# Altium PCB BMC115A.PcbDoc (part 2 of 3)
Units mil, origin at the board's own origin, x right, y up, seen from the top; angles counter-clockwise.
Board outline 5500 x 3200 mil, 4 copper layers (Top Layer, Signal Layer 1, Signal Layer 2, Bottom Layer), stack 61.6 mil thick; 199 components, 81 nets, 456 pads, 1349 vias.
Unrouted connection lines stored in the file: 741.
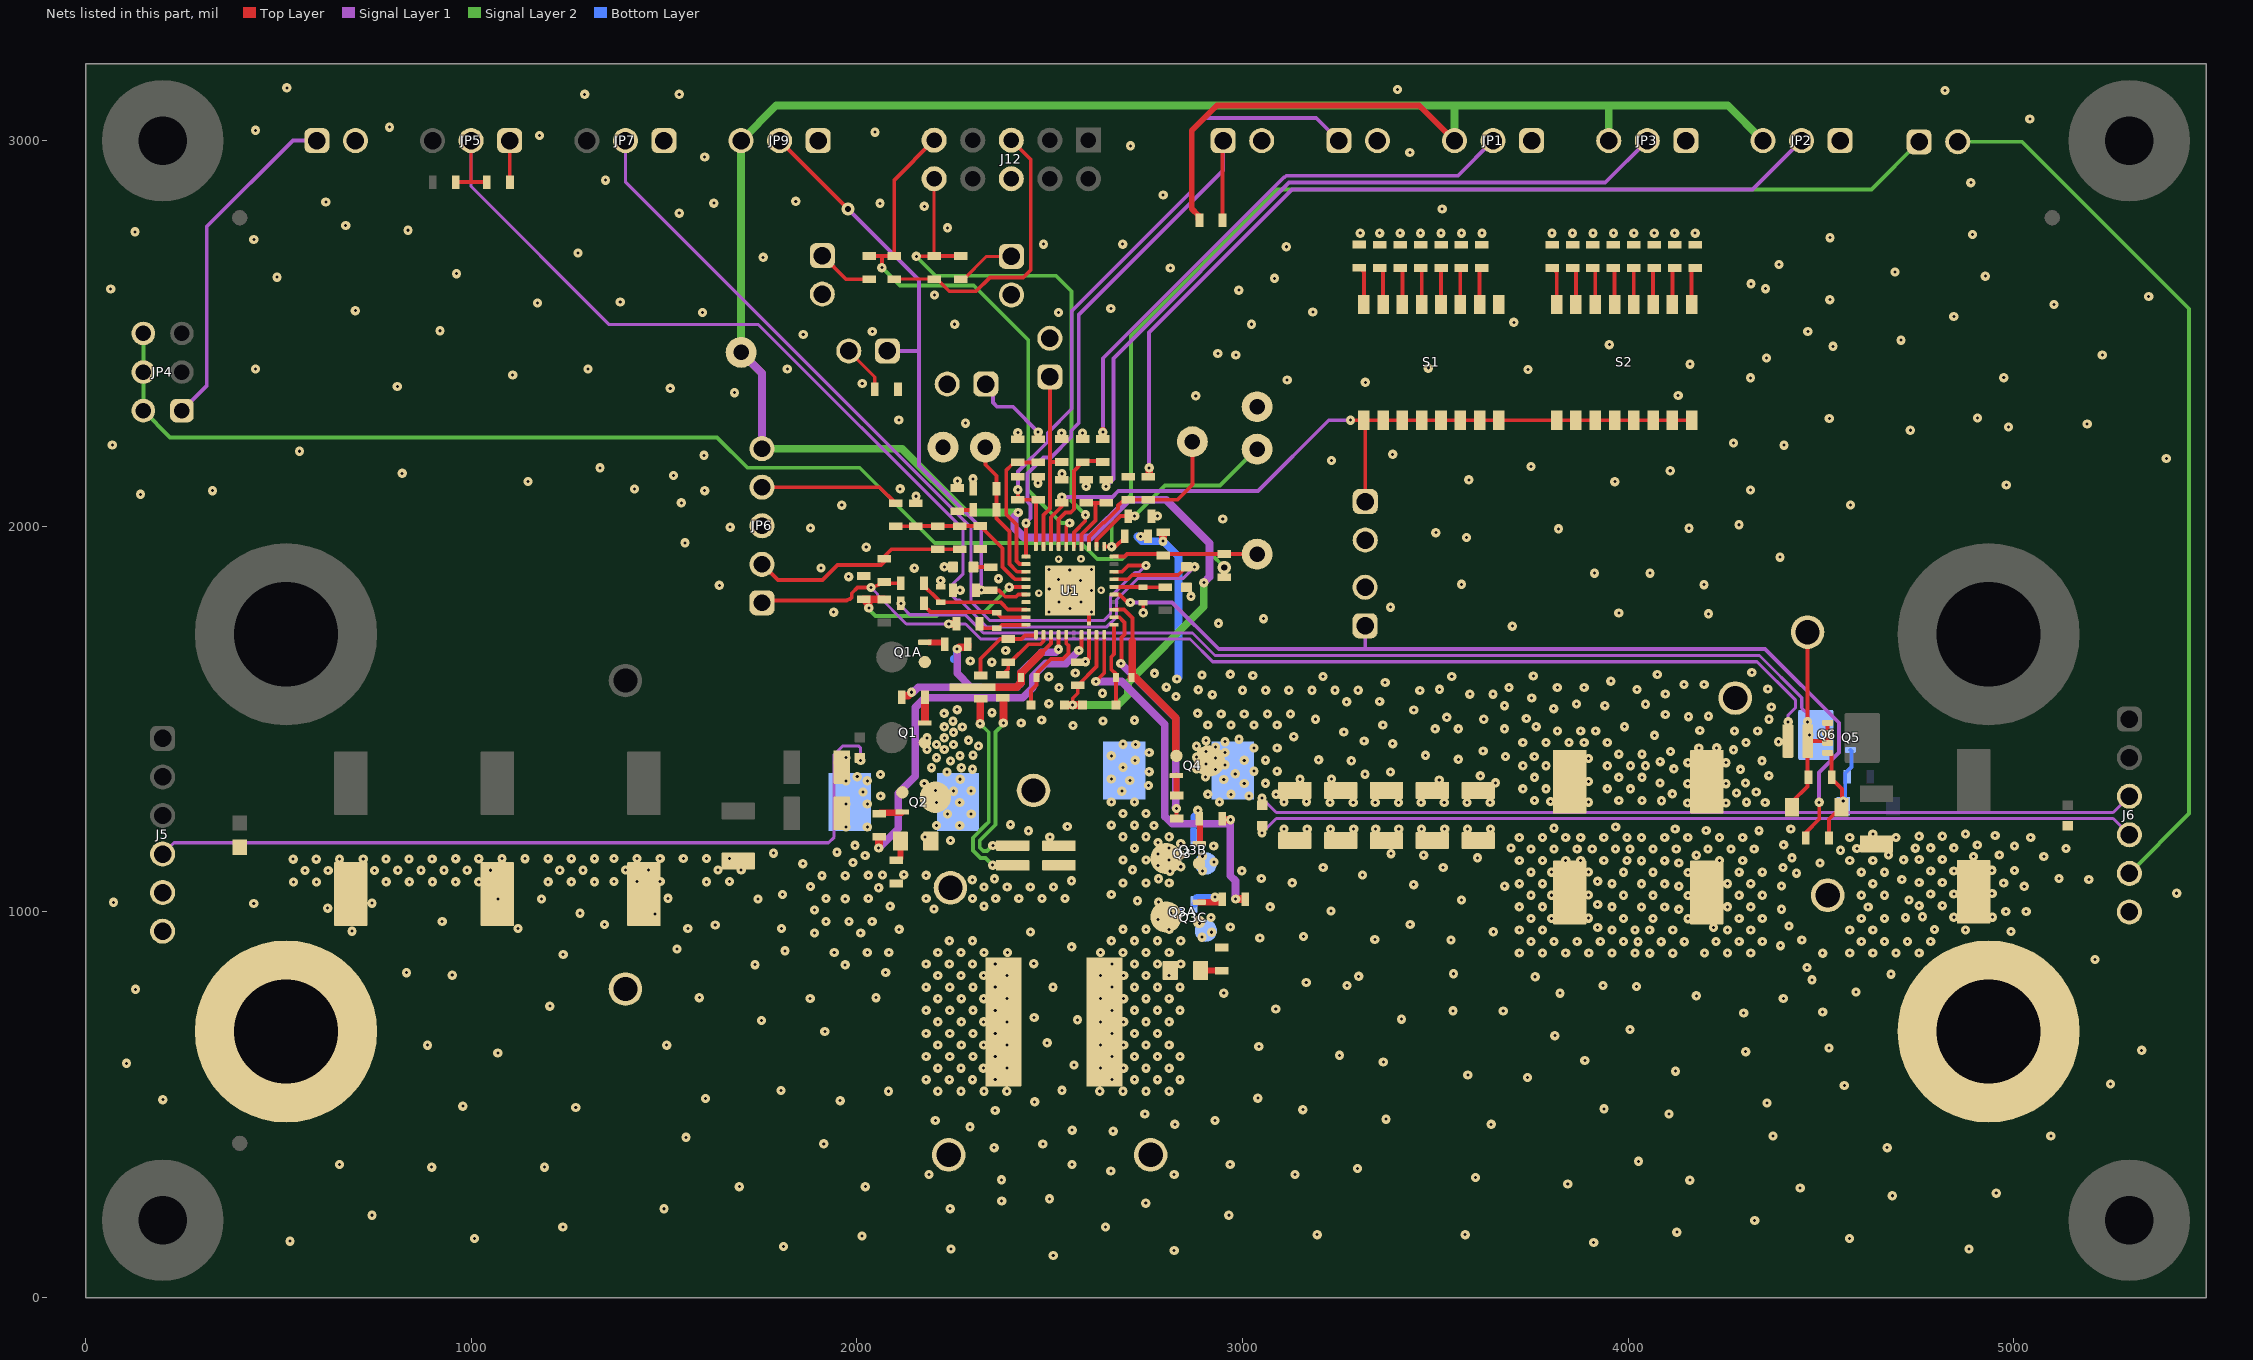
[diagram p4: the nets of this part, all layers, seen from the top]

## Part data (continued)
R30 R51: library part CMP-0023250-5, "RES, 6.49 k, 1%, 0.1 W, 0603", Manufacturer=Yageo, Power_W=100mW, Supplier Part Number 1=311-6.49KHRCT-ND, TempCo="100 ppm/C", Tolerance_%=1%, Value2=0.1W, Value_Code=6k49, ValueDisplayed=6.49k
R31 R52: library part CMP-0023307-5, "RES, 8.25 k, 1%, 0.1 W, 0603", Manufacturer=Yageo, Power_W=100mW, Supplier Part Number 1=311-8.25KHRCT-ND, TempCo="100 ppm/C", Tolerance_%=1%, Value2=0.1W, Value_Code=8k25, ValueDisplayed=8.25k
R32: library part CMP-0022000-4, "RES, 10.5 k, 1%, 0.1 W, AEC-Q200 Grade 0, 0603", Manufacturer=Vishay-Dale, Power_W=100mW, Supplier Part Number 1=541-10.5KHCT-ND, TempCo="100 ppm/C", Tolerance_%=1%, Value2=0.1W, Value_Code=10k5, ValueDisplayed=10.5k
R33: library part CMP-0022790-5, "RES, 13.3 k, 1%, 0.1 W, 0603", Manufacturer=Yageo, Power_W=100mW, Supplier Part Number 1=311-13.3KHRCT-ND, TempCo="100 ppm/C", Tolerance_%=1%, Value2=0.1W, Value_Code=13k3, ValueDisplayed=13.3k
R34: library part CMP-0022079-4, "RES, 16.2 k, 1%, 0.1 W, AEC-Q200 Grade 0, 0603", Manufacturer=Vishay-Dale, Power_W=100mW, Supplier Part Number 1=541-16.2KHCT-ND, TempCo="100 ppm/C", Tolerance_%=1%, Value2=0.1W, Value_Code=16k2, ValueDisplayed=16.2k
R35: library part CMP-0022905-5, "RES, 20.5 k, 1%, 0.1 W, 0603", Manufacturer=Yageo, Power_W=100mW, Supplier Part Number 1=311-20.5KHRCT-ND, TempCo="100 ppm/C", Tolerance_%=1%, Value2=0.1W, Value_Code=20k5, ValueDisplayed=20.5k
R36: library part CMP-0022237-4, "RES, 24.9 k, 1%, 0.1 W, AEC-Q200 Grade 0, 0603", Manufacturer=Vishay-Dale, Power_W=100mW, Supplier Part Number 1=541-24.9KHCT-ND, TempCo="100 ppm/C", Tolerance_%=1%, Value2=0.1W, Value_Code=24k9, ValueDisplayed=24.9k
R37: library part CMP-0022324-4, "RES, 30.1 k, 1%, 0.1 W, AEC-Q200 Grade 0, 0603", Manufacturer=Vishay-Dale, Power_W=100mW, Supplier Part Number 1=541-30.1KHCT-ND, TempCo="100 ppm/C", Tolerance_%=1%, Value2=0.1W, Value_Code=30k1, ValueDisplayed=30.1k
R38: library part CMP-0022352-4, "RES, 35.7 k, 1%, 0.1 W, AEC-Q200 Grade 0, 0603", Manufacturer=Vishay-Dale, Power_W=100mW, Supplier Part Number 1=541-35.7KHCT-ND, TempCo="100 ppm/C", Tolerance_%=1%, Value2=0.1W, Value_Code=35k7, ValueDisplayed=35.7k
R45: library part CMP-0022751-4, "RES, 10.0, 1%, 0.1 W, 0603", Manufacturer=Yageo, Power_W=100mW, Supplier Part Number 1=311-10.0HRCT-ND, TempCo="100 ppm/C", Tolerance_%=1%, Value2=0.1W, Value_Code=10R0, ValueDisplayed=10.0
R53: library part CMP-0025771-4, "RES, 2.7 k, 5%, 0.1 W, AEC-Q200 Grade 0, 0603", Manufacturer=Vishay-Dale, Power_W=100mW, Supplier Part Number 1=541-2.7KGCT-ND, TempCo="200 ppm/C", Tolerance_%=5%, Value2=0.1W, Value_Code=2k70, ValueDisplayed=2.7k
R54: library part CMP-0022410-4, "RES, 40.2 k, 1%, 0.1 W, AEC-Q200 Grade 0, 0603", Manufacturer=Vishay-Dale, Power_W=100mW, Supplier Part Number 1=541-40.2KHCT-ND, TempCo="100 ppm/C", Tolerance_%=1%, Value2=0.1W, Value_Code=40k2, ValueDisplayed=40.2k
R55: library part CMP-0025810-4, "RES, 43 k, 5%, 0.1 W, AEC-Q200 Grade 0, 0603", Manufacturer=Vishay-Dale, Power_W=100mW, Supplier Part Number 1=541-43KGCT-ND, TempCo="200 ppm/C", Tolerance_%=5%, Value2=0.1W, Value_Code=43k0, ValueDisplayed=43k
R60: library part CMP-0022852-5, "RES, 18.0 k, 1%, 0.1 W, 0603", Manufacturer=Yageo, Power_W=100mW, Supplier Part Number 1=311-18.0KHRCT-ND, TempCo="100 ppm/C", Tolerance_%=1%, Value2=0.1W, Value_Code=18k0, ValueDisplayed=18.0k
S1 S2: library part CMP-0002229-1, "Switch, SPST, 8 Pos, 25mA, 24VDC, SMD", CurrentRating_mA=25A, Manufacturer="CTS Electrocomponents", Supplier Part Number 1=CT2188LPST-ND
SH-JP1 SH-JP2 SH-JP3 SH-JP4 SH-JP5 SH-JP6 SH-JP7 SH-JP8 SH-JP9 SH-JP10 SH-JP11 SH-JP12: library part CMP-0078738-1, "Single Operation 2.54mm Pitch Open Top Jumper Socket", Manufacturer=Harwin, Supplier Part Number 1=952-2881-ND
TP1: library part CMP-0055147-2, "Test Point, Multipurpose, Red, TH", Color=Red, Manufacturer="Keystone Electronics", Supplier Part Number 1=36-5010-ND
TP2 TP8: library part CMP-0055150-2, "Test Point, Multipurpose, Orange, TH", Color=Orange, Manufacturer="Keystone Electronics", Supplier Part Number 1=36-5013-ND
TP3 TP4: library part CMP-0055148-2, "Test Point, Multipurpose, Black, TH", Color=Black, Manufacturer="Keystone Electronics", Supplier Part Number 1=36-5011-ND
TP5 TP6 TP9: library part CMP-0055149-2, "Test Point, Multipurpose, White, TH", Color=White, Manufacturer="Keystone Electronics", Supplier Part Number 1=36-5012-ND
TP7: library part CMP-0055159-2, "Test Point, Multipurpose, Grey, TH", Color=Grey, Manufacturer="Keystone Electronics", Supplier Part Number 1=36-5128-ND
TP10 TP11 TP12 TP13 TP15: library part CMP-0055141-2, "Test Point, Miniature, Yellow, TH", Color=Yellow, Manufacturer="Keystone Electronics", Supplier Part Number 1=36-5004-ND
TP14 TP16: library part CMP-0055138-2, "Test Point, Miniature, Black, TH", Color=Black, Manufacturer="Keystone Electronics", Supplier Part Number 1=36-5001-ND
U1: library part CMP-0120007-1, "48-V 4 Switch Buck-Boost Controller with I2C interface", Manufacturer="Texas Instruments", Max Supply Voltage=48V, Min Supply Voltage=3.3V, Nominal Supply Current=25uA, Operating Temperature Range="-40°C to +150°C", Output Voltage=3.3-48V, Switching Frequency=100-2200kHz
ZZ2: library part CMP-0077236-1
ZZ3: library part CMP-0077237-1
ZZ4: library part CMP-0077238-1

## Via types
v1: diameter 24, hole 7.87, Top Layer to Bottom Layer, tented both sides, 1320 vias
v2: diameter 19.68, hole 7.87, Top Layer to Bottom Layer, tented both sides, 17 vias
v3: diameter 24, hole 8, Top Layer to Bottom Layer, tented both sides, 8 vias
v4: diameter 34, hole 16, Top Layer to Bottom Layer, tented both sides, 2 vias
v5: diameter 19.68, hole 7.87, Top Layer to Bottom Layer, 2 vias

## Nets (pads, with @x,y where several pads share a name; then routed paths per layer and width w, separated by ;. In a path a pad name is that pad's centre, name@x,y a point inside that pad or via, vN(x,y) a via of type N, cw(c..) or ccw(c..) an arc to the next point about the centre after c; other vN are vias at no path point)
AGND: C17.1 C18.2 C19.2 C20.2 C26.1 C27.2 C28.2 C29.1 C33.2 C34.2 C35.2 C36.2 C37.2 C40.2 C42.2 J7.2 J8.2 J9.2 J10.2 J11.2 J12.6 J14.2 JP1.1 JP2.1 JP3.1 JP5.1 JP6.3 JP7.1 JP8.2 JP9.1 JP11.2 JP12.2 NT1.2 R2.1 R15.1 R18.1 R20.1 R21.1 R24.1 R25.1 R26.1 R27.1 R28.1 R29.1 R30.1 R31.1 R32.1 R33.1 R34.1 R35.1 R36.1 R37.1 R38.1 R53.1 R54.1 R60.1 S1.1 TP14.1 TP16.1 U1.17 U1.41 | length 750.5
  Top Layer w10: JP5.1@1100,3005.59 JP5.1@1100,3000 1100,2893.28 R15.1@1100.61,2892.68 ; R21.1@2417.7,2226.09 v1(2417.7,2242.78) ; v1(2469.92,2111.69) 2469.92,2128.38 R54.1@2470.26,2128.72 ; R53.1@2531.4,2120.8 2531.4,2135.12 v1(2532.47,2136.2) ; v2(2553,1786.46) v2(2553,1833) ; NT1.2@2602.22,1748.34 U1.41@2602.22,1777.88 ; U1.41@2602.54,1827.42 v2(2608.12,1833) ; C26.1@2742.37,1801.95 2742.89,1801.43 v1(2742.89,1775.77)
  Top Layer w20: v1(2736.27,1973.26) v1@2744.74,1973.26 ; v1(2794.32,1961.47) C29.1@2794.32,1980.94
  Bottom Layer w10: v1@2785.32,1961.47 v1@2789.82,1956.97 ; v1@2794.32,1956.97 v1(2794.32,1961.47)
  Bottom Layer w20: v1@2727.8,1973.26 2739.58,1961.47 v1@2785.32,1961.47 ; v1(2794.32,1961.47) 2834.46,1921.33 2834.46,1751.45 2834.46,1608.32 v1(2830.06,1603.93)
  other v1: 3699.82,1740.92 2938,1748.25 3054.7,1760.48 4208.74,1772.93 3976.22,1775.35 1940,1777.37 3384.3,1790.15 2866.87,1818.39 2268.12,1834.12 1643.69,1846.89 3567.96,1849.43 4196.73,1848.52 2217.64,1859.28 2367.43,1864.12 1978.89,1869.36 3913,1878.43 4057.2,1878.43 2149.19,1891.48 1907.45,1891.69 2227.11,1894.88 4394,1920 2024.57,1945.95 1554.27,1957.1 3581,1971 3501.46,1983.47 3819.87,1993.39 1880,1995.26 4158.2,1994.85 1671.75,1997.74 4287.79,2004 2949,2018.96 2780.08,2026.62 1961.04,2054.59 4577,2055 1544.89,2060.75 2153.61,2077.87 142.76,2082.92 329.47,2092.38 1605.68,2092.38 4317.87,2094.39 1423.63,2096.98 2112.63,2097.1 2594.9,2103.69 4981,2107 1147.19,2116.01 3965.7,2115.61 2261.32,2117.3 3587.09,2120.47 2301.57,2123.05 1524.46,2131.42 821.05,2137.28 4109.45,2144.01 1333.99,2151.71 3748.31,2154.78 3231.3,2170.36 5396,2176 1603.56,2184.13 3389.62,2186.52 554.7,2194.57 4404.53,2210.22 69.5,2210.55 4273.26,2215.74 2531.21,2241.64 2585.06,2241.64 4731.91,2249 4986.36,2257.23 5190.55,2265.13 2282.15,2267.3 2108.95,2275.74 4521.89,2279.2 4906.36,2280.53 2879.03,2338.4 4130,2339 1683.03,2346.39 1516.34,2357.88 808.47,2362.16 2014.15,2370.46 3318.61,2373.33 3116.18,2379.61 4317.87,2384.87 4974.29,2385.25 1107.63,2392.53 3740.61,2406.25 441,2407.8 1303.19,2407.81 1820,2407.81 3482.22,2410.07 4160.45,2420.36 4359.05,2436.35 2983.05,2443.91 5230,2444 2936.19,2447.84 4531.3,2466.78 3951.54,2470.99 4707.7,2482.66 1861.22,2497.46 2040.36,2504.95 4466.2,2505.04 918.97,2507.03 2253.75,2523.87 3023.48,2523.87 3703.74,2528.79 4844.8,2543.85 1600,2554.43 2523.35,2554.43 3182.74,2555.6 699.61,2558.99 2658.69,2564.84 5104.35,2575.07 1172.1,2579.13 1386.67,2581.55 4523.2,2587.48 5350,2596 2201.71,2599.94 2990.7,2612.39 65.22,2615.39 4356.47,2616.11 4318.82,2628.86 3083.19,2643 496.54,2645.86 4926.56,2648.5 962,2655 4692.23,2659.58 2813,2670 4391.69,2678.8 1757.39,2697.35 1277.24,2708.96 3113.92,2724.83 2484.4,2731.6 2689.41,2731.6 436.5,2743.89 4523.75,2748.47 4893.06,2756.42 3305.61,2760 3356,2760 3409,2760 3462,2760 3515,2760 3568,2760 3621,2760 3803,2760 3856,2760 3909,2760 3962,2760 4015,2760 4068,2760 4121,2760 4174,2760 128.58,2763.57 836.53,2767.7 2235,2774 674.65,2780.22 1539.59,2812 3518.03,2822.95 2175.13,2829.79 1629.17,2837.92 2060.46,2837.53 623.09,2841.07 1841.75,2842.72 2794.66,2858.75 4888.99,2891.02 1348.32,2897.44 1605.68,2957.29 3434,2969 2710.03,2986.57 1177.24,3013.64 2047.48,3021.84 441,3026.64 788,3034.95 5042.03,3056.39 1294.41,3120 1539.59,3120 4822.07,3129.89 3402.03,3132.39 522,3137
  other v2: 2497.88,1777.88 2608.12,1777.88 2524.33,1804.08 2581.35,1804.08 2472.01,1826.4 2633.77,1834.12 2499.08,1837.16 2580.27,1859.28 2523.47,1861.62 2552.26,1886.07 2497.88,1888.12 2608.12,1888.12 2523.35,1914.8 2581.35,1915.33
BIAS: C29.2 R57.1 TP15.1 U1.40 | length 382.5
  Top Layer w10: U1.40@2667.17,1921.58 2694.94,1921.58 2701.15,1927.79 ; 2694.71,1921.36 2701.15,1927.75 2794.32,1927.75 2954.56,1927.75 3037.84,1927.75 TP15.1@3038,1927.91
CDC: C42.1 J14.1 R54.2 U1.10 | length 1739.8
  Top Layer w10: v3(2417.7,2094.66) 2417.93,2094.43 C42.1@2417.93,2068.72 R54.2@2470.26,2068.72 2464.42,2062.87 U1.10@2464.42,1947.17
  Signal Layer 1 w10: v3(2417.7,2094.66) 2417.93,2094.89 2417.93,2142.03 2495.23,2219.33 2495.23,2242.29 2557.56,2304.62 2557.56,2558.56 2868.51,2869.51 2868.51,3026.04 2901.13,3058.67 3191.33,3058.67 J14.1@3250,3000
CFG2: J8.1 R53.2 S1.9 S1.10 S1.11 S1.12 S1.13 S1.14 S1.15 S1.16 S2.9 S2.10 S2.11 S2.12 S2.13 S2.14 S2.15 S2.16 U1.8 | length 2064.1
  Top Layer w10: U1.8@2503.79,1947.17 2503.79,2023.26 2531.4,2050.87 R53.2@2531.4,2060.8 2531.4,2075.56 v1(2531.84,2076.01) ; v1(3280,2275) S1.9@3315,2275 ; J8.1@3318.61,2068.72 3318.61,2271.39 S1.9@3315,2275 ; S2.16@4165,2275 S2.15@4115,2275 S2.14@4065,2275 S2.13@4015,2275 S2.12@3965,2275 S2.11@3915,2275 S2.10@3865,2275 S2.9@3815,2275 S1.16@3665,2275 S1.15@3615,2275 S1.14@3565,2275 S1.13@3515,2275 S1.12@3465,2275 S1.11@3415,2275 S1.10@3365,2275 3318.61,2275 S1.9@3315,2275
  Signal Layer 1 w10: v1(2531.84,2076.01) 2662.84,2076.01 2678.13,2091.3 2693.8,2091.3 2694.08,2091.59 2811.39,2091.59 2811.67,2091.3 3040.23,2091.3 3223.93,2275 v1(3280,2275)
COMP: C19.1 R19.2 TP13.1 U1.13 | length 380.1
  Top Layer w10: TP13.1@2333.66,2205.39 2333.66,2159.41 2362.19,2130.89 C19.1@2362.19,2097.1 R19.2@2362.19,2042.59 2362.19,2020.25 2396,1986.44 2396,1902.16 2415.94,1882.21 U1.13@2438.83,1882.21
CSA/SW1: C21.2 R11.1 U1.22 | length 169.5
  Top Layer w10: R11.1@2378,1615 2392.68,1629.68 C21.2@2392.68,1647.64 2398.68,1647.64 2445.19,1694.14 2476.26,1694.14 2484.1,1701.99 U1.22@2484.1,1718.83
CSB: C21.1 R12.1 U1.21 | length 212.8
  Top Layer w10: R12.1@2321,1613 2321,1656.45 2372.19,1707.64 C21.1@2392.68,1707.64 2392.81,1707.52 2426.67,1707.52 2436.11,1716.96 2462.55,1716.96 U1.21@2464.42,1718.83
DRV1: J11.1 R55.1 U1.35 | length 2413.3
  Top Layer w10: U1.35@2667.17,1823.16 2681.33,1823.16 v1@2701.87,1802.62 ; R55.1@4461.1,1198.3 4461.1,1205.8 4495.79,1240.49 4495.79,1257.73 v1(4495.79,1284.1)
  Signal Layer 1 w10: v1@2701.87,1802.62 2817.82,1802.62 2938.57,1681.87 3318.61,1681.87 ; J11.1@3318,1741.92 3318.61,1741.31 3318.61,1681.87 ; v1@4495.16,1276.51 4495.16,1361.86 4546.75,1413.45 4546.75,1490.64 4355.52,1681.87 3318.61,1681.87
  other v1: 2709.27,1802.62
DTRK: C36.1 R50.2 U1.4 | length 181.3
  Top Layer w10: U1.4@2582.53,1947.17 2582.53,1978.27 2619.5,2015.24 2619.5,2060.8 ; C36.1@2594.9,2060.8 2614.58,2060.8 2619.5,2060.8 ; R50.2@2647.23,2060.8 2619.5,2060.8
EN/UVLO: C28.1 JP5.2 R14.1 R15.2 U1.37 | length 3114
  Top Layer w8: 1000,2892.68 JP5.2@1000,3000
  Top Layer w10: R14.1@960.36,2892.68 1000,2892.68 R15.2@1040.61,2892.68 ; U1.37@2667.17,1862.53 2703.21,1862.53 2714.33,1873.65 2833.72,1873.65 C28.1@2854.99,1894.92 ; v1(2876.2,1894.88) v1(2876.2,1894.88)
  Top Layer w20: C28.1@2854.99,1894.92 v1(2876.2,1894.88)
  Signal Layer 1 w8: JP5.2@1000,3000 1000,2881.06 1358.18,2522.88 1745.1,2522.88 2275.8,1992.18 2275.8,1876.98 2243.24,1844.42 2243.24,1823.81 2257.82,1809.24 2266.29,1809.24 2336.27,1739.27 2648.52,1739.27 2673.36,1764.1 2673.36,1809.7 2727.78,1864.12 2845.44,1864.12 v1(2876.2,1894.88)
FB: C16.2 C37.1 R1.1 R2.2 R46.1 U1.14 | length 424.8
  Top Layer w10: R46.1@2100.43,1999.98 C37.1@2153.05,1999.98 2153.48,2000.42 C16.2@2209.91,2000.42 R1.1@2266.51,2000.42 2266.96,2000.86 R2.2@2320.21,2000.86 2378.12,1942.95 2378.12,1893.95 2405,1867.07 2405.68,1867.07 2410.22,1862.53 U1.14@2438.83,1862.53
FLT: J9.1 R16.1 U1.11 | length 1515.7
  Top Layer w10: U1.11@2438.83,1921.58 v1(2438.83,2007.96) ; R16.1@2948.51,2793.22 2948.51,2998.51 J9.1@2950,3000
  Signal Layer 1 w10: v1(2438.83,2007.96) 2438.83,2008.78 2450.87,2020.82 2450.87,2055.47 2442.57,2063.76 2442.57,2137.09 2484.2,2178.71 2503.46,2178.71 2556.08,2231.33 2556.08,2247.84 2575.44,2267.19 2575.44,2548.27 2950,2922.83 J9.1@2950,3000
GND: C1.2 C2.1 C3.1 C4.1 C5.1 C6.1 C7.2 C8.1 C9.1 C10.1 C11.1 C12.1 C13.1 C14.1 C15.1 C31.2 C32.2 C38.1 C39.1 C41.1 D2.2 J3.1 J4.1 J5.4 J5.5 J5.6 J6.4 J6.5 J6.6 J13.2 NT1.1 Q2.1-2-3 Q3.1-2-3 Q3A.1-2-3 Q3B.1-2-3-4 Q3C.1-2-3-4 R13.1 R39.1 TP3.1 TP4.1 U1.28 | length 6771
  Top Layer w10: v1(2498,1540) v1@2498.78,1540.78 ; v1(2593.31,1648.89) 2601.95,1657.53 2601.95,1673.61 2602.21,1673.88 U1.28@2602.21,1718.83
  Top Layer w25: C2.1@1952.58,1387.56 C2.1@1967.22,1372.92
  Signal Layer 1 w8: J5.4@200,1150 229.3,1179.3 1926.6,1179.3 1941.24,1193.94 1941.24,1204.22 1941.36,1204.35 1941.36,1408.37 1962.93,1429.94 2005.4,1429.94 2010.08,1425.26 v1(2010.08,1392.48) ; v1(3051,1205) 3088.04,1242.04 5257.96,1242.04 J6.4@5300,1200
  Signal Layer 2 w10: J13.2@4855,2997 5022,2997 5455,2564 5455,1255 J6.5@5300,1100
  other v1: 2509.48,109.05 2823.15,121.96 2244.33,125.84 4884.1,125.84 1809.98,132.58 3911.03,142.68 530.5,146.05 1008.62,152.78 4574.34,152.78 2013.8,159.39 3193.84,162.88 3577.69,162.88 4126.52,169.61 1237.58,183.08 2645.01,183.08 4328.54,199.92 742.62,213.39 2964.88,213.39 1500.21,230.22 2242.28,230.39 2749.39,244.8 2375.65,250.42 2500,256 4685.45,263.89 4954.81,270.63 4446.39,284.09 1695.5,287.46 2022.11,287.46 3843.68,294.2 4160.19,304.3 3604.62,311.03 3136.6,318.88 3298.22,334.6 897.51,337.97 1190.44,337.97 658.45,344.7 2558.1,344.7 2968.25,344.7 4026.89,353.33 4671.98,388.47 2482.53,398.02 1914.36,398.57 1557.45,415.41 4375.68,418.78 5096.23,418.78 2558.42,434.1 3645.03,449.08 2929,458.86 3372.3,462.55 4106.31,476.02 3156.8,487.23 3937.96,489.49 1271.25,492.85 978.32,496.22 4360.15,504.61 2461.38,507.5 1957.01,510.5 200.53,513.05 1607.96,516.42 3040.01,516.95 2082.22,534.89 1803.25,536.62 2532.3,537.36 4560.87,550.09 5251.11,553.46 3739.31,570.29 3584.42,577.03 4123.34,587 2563.4,603.3 106.25,607.33 3365.56,610.7 3888.02,614.59 3251.71,627.96 1069.23,634.27 4304.97,637.64 5331.92,641 4521.1,646.78 3042.59,651.2 887.05,654.47 1506.95,654.47 2493.73,660.53 3810.23,678.97 1916.99,689.92 4005.3,694.88 1752.74,718.45 2572.11,720.25 3412.7,721.81 2460.14,726.47 4299.79,737.99 4504.83,740.17 3545.99,743.35 3676.39,742.84 3086.48,748.01 1203.91,755.48 1879.04,775.27 4402.62,775.68 1591.7,777.7 2049.95,777.7 4177.02,782.42 2951.65,789.15 3823.48,789.15 4591.17,792.52 129.82,799.25 2508.66,804.85 4022.15,806.4 3271.28,809.36 3934.97,809.08 3165.56,817.2 4476.84,823.83 3759.26,831.88 3301.59,832.92 951,836 4682.06,838.59 3547.38,839.66 832.64,842.53 2075,843 4464.32,856.02 1735.91,863.23 1969.91,862.89 2458.89,865.82 5210.71,876.7 1238.65,889.47 3718.2,893.16 3778.2,893.16 3838.2,893.16 3898.2,893.16 3958.2,893.16 4018.2,893.16 4055.99,892.91 4115.99,892.91 4198.2,893.16 4258.2,893.16 4318.2,893.16 4504.83,892.91 4574.92,893.16 4634.92,893.16 4694.92,893.16 4754.92,893.16 1941.57,895 2027.35,894.89 2083.08,895 1813.72,899.04 1533.88,903.63 2557.18,909.36 4395.12,912.43 3748.2,923.16 3808.2,923.16 3868.2,923.16 3928.2,923.16 3988.2,923.16 4025.99,922.91 4085.99,922.91 4145.99,922.91 4228.2,923.16 4288.2,923.16 4348.2,923.16 4604.92,923.16 4664.92,923.16 4724.92,923.16 4784.92,923.16 3540.63,927.11 4450.81,927.11 3343.46,928.45 3045.17,932.6 2894.99,934.49 3158.36,936.5 1890.08,945 2010,945 2920.25,947.28 2450.18,947.93 3650.61,948.57 4993.25,949.05 690.73,950 3718.2,953.16 3778.2,953.16 3958.2,953.16 4018.2,953.16 4055.99,952.91 4115.99,952.91 4258.2,953.16 4318.2,953.16 4574.92,953.16 4634.92,953.16 4874.92,953.16 4794.92,954.16 2109.98,954.89 1121.7,957 1562,957 1805.06,956.86 3921.39,959.25 4221.39,959.25 2968.79,960.86 4417.38,963.33 1633.01,966.16 1345.66,967.61 3434.93,967.61 2888.17,970.51 924.88,975.12 1920.08,975 1980,975 2040,975 4155.62,982.32 3748.2,983.16 3801.72,983.16 3988.2,983.16 4064.99,982.91 4288.2,983.16 4348.2,983.16 4604.92,983.16 4664.92,983.16 3897.57,983.75 4719.21,985.11 2918.68,985.67 4844.92,986.16 4945.35,986.19 4763.5,987.44 1476.64,994.54 1282.29,996.53 4979.56,1000.86 5032.48,1000.84 3229.76,1002.3 1890.08,1005 4131.8,1006.82 4397.76,1006.88 628,1009.66 3071.93,1013.31 3718.2,1013.16 3778.2,1013.16 3958.2,1013.16 4034.99,1012.91 4094.99,1012.91 4258.2,1013.16 4318.2,1013.16 4622.6,1012.95 2086.49,1014.9 4754.92,1016.16 4814.92,1016.16 3921.39,1019.25 436.22,1021.48 742.62,1022.68 72.58,1024.85 3567.96,1030.7 4728.28,1030.7 1069.23,1033.28 1182.48,1033.28 1744.02,1033.28 1970.08,1034 1510.41,1035.23 1920.08,1035 2030,1034.89 4155.62,1042.32 3748.2,1043.16 3801.72,1043.16 3988.2,1043.16 4064.99,1042.91 4288.2,1043.16 4348.2,1043.16 4604.92,1043.16 4664.92,1043.16 3897.57,1043.75 1807.31,1044.89 4784.92,1046.16 4844.92,1046.16 4944.37,1047.77 5422.83,1048.42 2056.71,1062.59 1880,1066 5027.46,1066.35 3680.12,1066.6 4131.8,1066.82 4397.76,1066.88 3444.06,1070.63 3718.2,1073.16 3778.2,1073.16 3958.2,1073.16 4034.99,1072.91 4094.99,1072.91 4258.2,1073.16 4318.2,1073.16 4634.92,1073.16 3129.23,1075.35 4974.12,1075.21 4754.92,1076.16 4814.92,1076.16 539.1,1077.58 599.1,1077.58 779.73,1077.99 839.73,1077.99 899.73,1077.99 959.73,1077.99 1019.73,1077.99 1199.73,1077.99 1259.73,1077.99 1319.73,1077.99 1610.22,1077.99 1370.22,1078.76 1430.22,1078.76 1490.22,1078.76 1670.22,1078.76 3921.39,1079.25 4710.12,1084.22 5194.99,1084.16 3049.04,1086.89 5117.38,1086.87 1910.08,1094 1970.08,1094 2030,1094.89 2066.73,1095.85 3311.63,1095.56 2121.96,1096.53 4437.18,1100.49 4155.62,1102.32 3748.2,1103.16 3801.72,1103.16 3988.2,1103.16 4064.99,1102.91 4288.2,1103.16 4348.2,1103.16 4604.92,1103.16 4664.92,1103.16 3897.57,1103.75 2998.35,1106.44 4784.92,1106.16 4844.92,1106.16 569.1,1107.58 629.1,1107.58 749.1,1107.58 809.73,1107.99 869.73,1107.99 929.73,1107.99 989.73,1107.99 1049.73,1107.99 1229.73,1107.99 1289.73,1107.99 4944.12,1107.71 5002.36,1107.66 1400.22,1108.76 1460.22,1108.76 1640.22,1108.76 1700.22,1108.76 3209.33,1114.89 3520.51,1114.89 4401.79,1115.39 1860.08,1125 4131.8,1126.82 4497.95,1126.82 1989.94,1128.39 3718.2,1133.16 3778.2,1133.16 3838.2,1133.16 3877.2,1133.16 3937.2,1133.16 3997.2,1133.16 4034.99,1132.91 4094.99,1132.91 4237.2,1133.16 4297.2,1133.16 4574.92,1133.16 4634.92,1133.16 4714.92,1135.16 4754.92,1136.16 4814.92,1136.16 538.35,1136.82 598.35,1136.82 658.35,1136.82 720.22,1137.23 778.98,1137.23 838.98,1137.23 898.98,1137.23 959.73,1137.99 1019.73,1137.99 1079.73,1137.99 1139.73,1137.99 1199.73,1137.99 1259.73,1137.99 1319.73,1137.99 1370.22,1138.76 1430.22,1138.76 1490.22,1138.76 1550.22,1138.76 1610.22,1138.76 1670.22,1138.76 3609.42,1140.37 4425.01,1140.16 4895.97,1143.62 5078.28,1143.57 2021.8,1146.44 3469.93,1147.08 4177.02,1147.08 4675.58,1147.47 4962.94,1147.47 3385.43,1151.1 1784,1152.37 1948.65,1154.92 4550.67,1159.84 3748.2,1163.16 3808.2,1163.16 3868.2,1163.16 3907.2,1163.16 3967.2,1163.16 4004.99,1162.91 4064.99,1162.91 4124.99,1162.91 4207.2,1163.16 4267.2,1163.16 4327.2,1163.16 4593.37,1164.27 5135.6,1164.27 4744.92,1165.16 3696.22,1165.86 4784.92,1166.16 4844.92,1166.16 5002.04,1170.93 1995.43,1172.72 4905.89,1173.33 4403.52,1173.97 3718.2,1193.16 3778.2,1193.16 3838.2,1193.16 3877.2,1193.16 3937.2,1193.16 3997.2,1193.16 4034.99,1192.91 4094.99,1192.91 4154.99,1192.91 4237.2,1193.16 4297.2,1193.16 4574.92,1193.16 4694.92,1193.16 5044.12,1193.21 4754.92,1196.16 4814.92,1196.16 4952.19,1198.3 4634.92,1201.76 4874.85,1202.05 4202.62,1211.03 4339.53,1210.57 3107.89,1214.92 3167.89,1214.92 3228.46,1214.92 3288.46,1214.92 3345.46,1214.92 3405.46,1214.92 3464.46,1214.92 3524.46,1214.92 3583.46,1214.92 3643.46,1214.92 4122.11,1215.12 4422.18,1214.92 3808.2,1216.94 1971.92,1220 2027.35,1220 3967.92,1220.12 1971.92,1280 2027.35,1280 2061.85,1300.32 2016.38,1310.81 1971.92,1340 2027.35,1340 2001.24,1350.55 2061.5,1356.35 1971.92,1400 2560.75,1483.26 2426.3,1490 2638.59,1495 2720.08,1496.81 2479.47,1497.7 2350.33,1516.5 2827.78,1558.31 2637.23,1566.99 2524.33,1581.97 2802.73,1582.63 2498,1609.89 2566.73,1619.34 2772.32,1618.65 2350.12,1647.49 2294.35,1650.53 2386.09,1677.64
  other v3: 2896.55,1106.59 2926.39,1129.34 2896.55,1144.38 2925.43,1170.68
HB1: C24.2 D3.1 U1.25 | length 239.8
  Top Layer w10: D3.1@2451.69,1540 2451.69,1574.03 2465.94,1588.28 2465.94,1608 2468.48,1610.54 2468.48,1620.37 2503.75,1655.64 2534.94,1655.64 2548.98,1669.68 2548.98,1690.39 2543.16,1696.21 U1.25@2543.16,1718.83
HB2: C25.2 D4.1 U1.31 | length 215.7
  Top Layer w10: U1.31@2667.17,1744.42 2667.17,1668.47 2659.92,1661.22 2659.92,1654.64 2659.92,1629.03 2672.04,1616.91 C25.2@2672.04,1608 ; D4.1@2672.31,1536.5 C25.2@2672.31,1607.74
HO1: R7.1 R58.1 U1.24 | length 699.8
  Top Layer w10: v1(2523.35,1680.84) 2523.47,1680.97 U1.24@2523.47,1718.83
  Top Layer w20: R7.1@2116.89,1556 2116.89,1560.33 2132.74,1560.33 v1(2142.01,1569.6) ; v1(2260.37,1682.02) 2261.46,1682.02 2266.08,1686.64 2288.08,1686.64 R58.1@2288.08,1694.14
  Signal Layer 1 w20: v1(2142.01,1569.6) 2145.8,1569.6 2159.14,1582.94 2296.05,1582.94 ; v1(2260.37,1682.02) 2260.37,1618.62 2296.05,1582.94 ; v1(2523.35,1680.84) 2515.77,1673.27 2479.21,1673.27 2425.94,1620 2425.94,1593.59 2415.29,1582.94 2296.05,1582.94
  Bottom Layer w20: 2251.12,1655.68 2258.62,1655.68 2258.62,1663.18 2259.61,1664.17 2259.61,1681.25 v1(2260.37,1682.02)
HO1_G: Q1.4 R7.2 | length 61.4
  Top Layer w20: Q1.4@2176.89,1494.63 R7.2@2176.89,1556
HO2: R8.1 U1.32 | length 604
  Top Layer w10: U1.32@2667.17,1764.1 2681.27,1764.1 2691.86,1753.52 2691.86,1753.33 2694.12,1751.07 2694.12,1719.22 2686.13,1711.22 2686.13,1650.67 v1@2679.79,1644.33 ; R8.1@2829.13,1242 v1@2829.13,1267.82
  Signal Layer 1 w20: v1(2684.79,1644.33) 2827.13,1502 2827.13,1270.8 v1@2826.75,1270.43
  other v1: 2828.97,1267.97
HO2_G: Q4.4 R8.2 | length 53.9
  Top Layer w10: R8.2@2826.85,1300.32 R8.2@2828.83,1302.3
  Top Layer w15: R8.2@2828.83,1302.3 Q4.4@2828.83,1353.45
ILIMCOMP: C33.1 JP9.2 JP10.1 R17.2 U1.16 | length 1602.9
  Top Layer w10: JP9.2@1800,3000 v4(1977.44,2822.56) ; C33.1@2309.35,1834.12 R17.2@2347.75,1834.12 2368.48,1834.12 2370.51,1832.09 2370.51,1831.89 2385.08,1817.32 2412.73,1817.32 2418.56,1823.16 U1.16@2438.83,1823.16
  Signal Layer 1 w10: v4(1977.44,2822.56) 2161.08,2638.92 2161.08,2454.69 ; JP10.1@2079.27,2454.69 2161.08,2454.69 ; v1(2322.86,1834.45) 2322.86,1995.15 2314.6,2003.4 2314.6,2003.94 2161.08,2157.46 2161.08,2454.69
ISNSN: C30.1 R43.1 U1.19 | length 282.9
  Top Layer w10: R43.1@2174.38,1800 2174.38,1793.86 2190.87,1777.37 2361.06,1777.37 C30.1@2362.79,1775.65 2374.33,1764.1 U1.19@2438.83,1764.1
ISNSP: C30.2 R42.1 U1.20 | length 128.8
  Top Layer w10: R42.1@2318.38,1747 2329.73,1735.65 C30.2@2362.79,1735.65 2368.01,1735.65 2376.78,1744.42 U1.20@2438.83,1744.42
LO1: R9.2 U1.27 | length 974.7
  Top Layer w10: v1(2575.89,1677.64) 2582.53,1684.28 U1.27@2582.53,1718.83
  Top Layer w20: v1(2056.81,1165.86) 2057.57,1166.62 2057.57,1187.81 R9.2@2058.6,1188.84
  Signal Layer 1 w20: v1(2056.81,1165.86) 2057.89,1165.86 2107.65,1215.62 2107.65,1307.93 2151.7,1351.98 2151.7,1529.97 2176.8,1555.06 2430.45,1555.06 2456.55,1581.17 2456.55,1611.19 2489.69,1644.33 2542.58,1644.33 v1(2575.89,1677.64)
LO1_G: Q2.4 R9.1 | length 61.2
  Top Layer w10: R9.1@2058.6,1254.84 R9.1@2060.99,1257.23 ; Q2.4@2116.45,1257.23 Q2.4@2118.14,1258.92
  Top Layer w16: R9.1@2060.99,1257.23 Q2.4@2116.45,1257.23
LO2: R10.2 R59.2 U1.30 | length 1018.5
  Top Layer w10: v1(2619.82,1597.43) 2641.58,1619.19 U1.30@2641.58,1718.83
  Top Layer w20: R10.2@2949,1238.94 v1(2969,1238.94) ; v1(2982.45,1033.22) R59.2@3007.58,1033.22
  Signal Layer 1 w20: v1(2619.82,1597.43) 2687.27,1597.43 2798.69,1486.01 2798.69,1247.58 2817.82,1228.45 2958.51,1228.45 ; v1(2969,1238.94) 2968.48,1238.42 2968.48,1094.07 2982.33,1080.22 2982.33,1033.34 v1(2982.45,1033.22)
LO2_G: Q3.4 Q3B.9 R10.1 | length 156.9
  Top Layer w10: Q3.4@2887.69,1176.67 Q3.4@2888,1176.97
  Top Layer w16: v1(2884.34,1263.33) 2884.34,1261.16 2886,1259.5 2886,1243.94 R10.1@2888,1241.94 ; Q3.4@2889.66,1181.39 R10.1@2889.66,1241.94
  Bottom Layer w16: Q3B.9@2873.11,1189.54 2873.11,1246.64 v1@2884.34,1257.86
MODE: C34.1 R47.2 U1.7 | length 305.2
  Top Layer w10: U1.7@2523.47,1947.17 2523.47,2017.67 2535.88,2030.07 2541.68,2035.87 2554.72,2035.87 2562.84,2044 2562.84,2143.53 C34.1@2585.69,2166.38 ; C34.1@2585.69,2169.38 2637.96,2169.38 R47.2@2638.15,2169.57
NetC7_1: C7.1 C8.2 C9.2 C10.2 C11.2 C12.2 C13.2 C41.2 D1.1 J6.3 JP6.1 Q4.5-6-7-8 R6.1 R41.2 R42.2 R45.2 TP8.1 | length 5244.4
  Top Layer w10: JP6.1@1754.31,1801.32 1770.55,1807.86 1973.51,1807.86 1982.61,1811.28 1987.07,1815.74 1987.07,1826.35 2001.74,1841.01 v1(2037.13,1841.01) 2057.47,1848.65 R45.2@2058.29,1848.65 ; R45.2@2081.16,1852.1 2083.29,1852.13 2109.38,1852.6 R41.2@2114.38,1852.68
  Top Layer w20: v1(2238.45,1746.7) R42.2@2258.08,1746.7
  Signal Layer 1 w8: v1(2037.13,1841.01) 2053.55,1824.6 2053.55,1821.83 2128.67,1746.7 v1(2238.45,1746.7) 2282.19,1746.7 2321.37,1707.52 2863.94,1707.52 2922.75,1648.71 4334.61,1648.71 4434.65,1548.67 4434.65,1529.99 4415.29,1510.63 v1(4415.29,1493) ; v1(3051,1295) 3088.08,1257.92 5257.92,1257.92 J6.3@5300,1300
  other v1: 4154.79,1282.63 4253.85,1282.57 3227.46,1283.92 3287.46,1283.92 3344.46,1283.92 3404.46,1283.92 3463.46,1283.92 3523.46,1283.92 3582.46,1283.92 3642.46,1283.92 4307.35,1284.41 4355.51,1283.87 2940.3,1284.89 3107.92,1285.39 3897.57,1284.67 3166.09,1285.78 3799.13,1286.56 4086.84,1288.2 3757.22,1289.04 3976.22,1289.04 4036.22,1289.04 3016.88,1300.32 2910.3,1304.81 2970.3,1304.81 3087.3,1304.81 4114.93,1306.09 4281.44,1308.26 4332.51,1310.66 3727.22,1319.04 3787.22,1319.04 3946.22,1319.04 4006.22,1319.04 4154.86,1332.46 4253.85,1332.41 3004.82,1333.03 3060.03,1333.42 4082.78,1334.2 4304.37,1334.2 3656.43,1334.81 3897.57,1337.94 3510.43,1342.34 2951.65,1343.05 3149.36,1343.99 3231.3,1344.89 3757.22,1349.04 3976.22,1349.04 4036.22,1349.04 2904.5,1349.65 3616.89,1352.79 4364.98,1353.14 3318,1357 2981.46,1358.2 3384.3,1363.02 3030.3,1364.81 3090.3,1364.81 2930.02,1368.97 4291.38,1369.64 2881.05,1371.33 4118.77,1370.99 3727.22,1379.04 3787.22,1379.04 3946.22,1379.04 4006.22,1379.04 4045,1379.04 2954.56,1381.53 2905.59,1383.89 4154.92,1387.1 4253.85,1387.05 4083.33,1389.66 3282.36,1391.98 4347.66,1391.83 3004.82,1393.03 3060.03,1393.42 3197.86,1394.4 3559.86,1395.74 3897.57,1397.94 2930.24,1398.83 2881.27,1401.19 3682.27,1403.23 3756.91,1403.23 3475,1406.14 3976.22,1409.04 4036.22,1409.04 2954.56,1413.37 2905.59,1415.72 4110.11,1415.91 3624.41,1417.29 4273.53,1420.23 3030.3,1424.81 3090.3,1424.81 4183.6,1424.88 4229.98,1425.42 2930.02,1427.48 2881.05,1429.83 3389.62,1436.33 3727.22,1439.04 3787.22,1439.04 3847.22,1439.04 3886.22,1439.04 3946.22,1439.04 4306.22,1439.04 4390.15,1441.29 2954.56,1441.53 3315.68,1443.28 2905.59,1443.89 2991.41,1448.03 3133.12,1454.47 4068.87,1457.82 3263.07,1466.61 3817.22,1469.04 3877.22,1469.04 3916.22,1469.04 4276.22,1469.04 4336.22,1469.04 4186.25,1470.37 3499.86,1474.67 3559.86,1474.67 3679.86,1474.67 3761.84,1480.37 3990.92,1480.23 2910.3,1484.81 2970.3,1484.81 3030.3,1484.81 3090.3,1484.81 3364.07,1484.81 3189.71,1499.6 3625.89,1499.6 4365.73,1499.6 3736.22,1501.29 3529.86,1504.67 4156.68,1506.21 4208.38,1507.59 4096.58,1512.13 2944.82,1513.03 3004.82,1513.03 3064.82,1513.03 3124.82,1513.03 2884.15,1515 3444.36,1523.67 3807.18,1527.06 4371.5,1531.29 3679.86,1534.67 3939.89,1534.72 4045.57,1538.47 3866.12,1538.95 3270.3,1544.81 3355.85,1545.41 3750.04,1554.43 2921.86,1563.34 3589.86,1564.67 3649.86,1564.67 4096.65,1565.35 3460,1574.03 3000.3,1574.81 3060.3,1574.81 3120.3,1574.81 3180.3,1574.81 3240.3,1574.81 3300.3,1574.81 2885.77,1576 3511.2,1577.13 4023.17,1577 4362.6,1577.73 3691.09,1581.96 3816.71,1581.96 3886.2,1581.96 4197.5,1589.39 4145.03,1589.54 3370.34,1595.2 3955.44,1598.27 3209,1610.52 3542.91,1610.52 3754.28,1611.54 3026.92,1613.3 2895.48,1614.27 2968.79,1616.08 4075.93,1615.63 4321,1620.73
NetC16_1: C16.1 JP6.2 R1.2 R45.1 | length 570.6
  Top Layer w10: JP6.2@1754.31,1901.32 1795.25,1860.37 1911.32,1860.37 1950.45,1899.51 2062.86,1899.51 2072.77,1909.41 2072.77,1923.56 2089.63,1940.42 C16.1@2209.91,1940.42 R1.2@2266.51,1940.42
NetC18_1: C18.1 R19.1 | length 37.6
  Top Layer w10: C18.1@2264.56,2042.59 R19.1@2302.19,2042.59
NetC22_1: C22.1 R13.2 | length 58.1
  Top Layer w10: R13.2@2102.27,1133.58 2108.27,1133.58 R13.2@2113.27,1138.58
  Top Layer w16: R13.2@2113.27,1138.58 C22.1@2113.27,1183.61
NetC22_2: C22.2 D2.1 NT2.2 Q1.1-2-3 Q1A.1-2-3 Q2.5-6-7-8 R3.2 R4.2 R11.2 TP5.1 | length 461.1
  Top Layer w20: R11.2@2378,1555 2380.21,1555 2380.21,1490.21 v1(2380,1490)
  Signal Layer 2 w10: v1(2352.66,1172.48) 2337.77,1157.59 2327.92,1157.59 2318.89,1166.62 2318.89,1184.8 2360.08,1226 2360.08,1466.58 2380,1486.5 v1(2380,1490) ; v1@2360.08,1171 v1@2360.08,1172.48
  other v1: 2242.77,1185.16 2176.73,1193.99 2500.64,1193.99 2445.19,1210.36 2546.07,1221.52 2206.73,1223.99 2266.73,1223.99 2398.44,1226.21 2235.56,1253.99 2296.73,1253.99 2206.73,1283.99 2266.73,1283.99 2251.12,1312.99 2296.73,1313.99 2203.68,1314.96 2175,1333.03 2268.12,1343.99 2233.98,1362.86 2300.24,1370 2193.72,1373.99 2271.08,1373.99 2243.34,1391.21 2206.73,1400 2267.61,1405.27 2301.08,1406.33 2182.19,1421.43 2227.11,1421.43 2315.91,1430.22 2206.73,1433.99 2251.12,1434.26 2289.97,1445 2182.41,1451.29 2227.11,1451.29 2251.12,1465.82 2227.11,1479.93 2273.62,1479.68 2249.57,1494.55 2226.75,1514.91 2260.37,1524.33
NetC23_1: C23.1 R39.2 | length 55.6
  Top Layer w10: C23.1@2891.6,841.09 C23.1@2891.66,841.15 ; C23.1@2891.66,848.15 C23.1@2892.13,847.68
  Top Layer w16: C23.1@2892.13,847.68 R39.2@2946.94,847.68
NetC26_2: C26.2 R40.1 U1.36 | length 133.5
  Top Layer w10: U1.36@2667.17,1842.84 2741.47,1842.84 C26.2@2742.37,1841.95 R40.1@2800.28,1841.92
NetC27_1: C27.1 R41.1 U1.18 | length 291.6
  Top Layer w10: R41.1@2174.47,1852.68 2174.47,1844.92 2186.39,1833 2186.65,1833 2189.28,1830.37 2189.71,1830.37 2197.25,1822.83 C27.1@2216.93,1803.16 ; C27.1@2222.79,1803.16 2372.95,1803.16 2380.08,1796.02 2387.66,1788.48 ; 2387.66,1788.44 2392.32,1783.79 U1.18@2438.83,1783.79
NetC40_1: C40.1 R17.1 | length 45.5
  Top Layer w10: C40.1@2302.69,1894.12 R17.1@2347.75,1894.12 ; C40.1@2312.38,1894.43 C40.1@2312.69,1894.12
NetD5_1: D5.1 Q5.1 Q5.2 Q5.3 Q6.5 Q6.6 Q6.7 Q6.8 Q6.9@4486.87,1459.16 R5.2 R6.2 R43.2 TP2.1 | length 3010.8
  Top Layer w10: D5.1@4425.63,1279.73 4425.63,1285.73 4465.39,1325.49 R5.2@4465.39,1334.36 ; v1(4465.29,1493) 4465.29,1725.29 TP2.1@4465.49,1725.49 ; R5.2@4465.39,1354.04 4465.39,1442.5 R6.2@4465.88,1443 4512.87,1443 Q5.3@4517.58,1438.29 4517.58,1443 Q5.2@4517.58,1464.29 Q5.1@4517.58,1490.29
  Signal Layer 1 w8: v1@2108.77,1799.42 2110.63,1799.42 2120.25,1789.8 2120.25,1787.94 2137.56,1770.63 2281.04,1770.63 2328.28,1723.39 2870.52,1723.39 2928.92,1664.99 4340.78,1664.99 4450.52,1555.24 4450.52,1528.44 4465.29,1513.67 v1(4465.29,1493)
  other v1: 2114.38,1800
  other v5: 4470.93,1459.16 4521.12,1459.16
NetD5_2: D5.2 D6.2 Q5.4 Q6.4 R5.1 R55.2 R56.1 | length 387.8
  Top Layer w10: Q5.4@4517.58,1412.29 4524.08,1412.29 4528.01,1408.35 R5.1@4528.01,1349.04 4528.01,1341.54 4533.01,1336.54 4536.77,1336.54 4554.57,1318.74 D5.2@4554.57,1279.73 ; R55.2@4521.1,1198.3 4521.1,1240.26 D5.2@4554.57,1273.72
  Bottom Layer w10: D6.2@4554.57,1286.72 4563.37,1295.52 4563.37,1360.24 4579.14,1376.01 4579.14,1417.66 Q6.4@4576.64,1420.16
  other v3: 4557.99,1287.25
NetJ10_1: J10.1 R49.2 | length 223.2
  Top Layer w20: R49.2@2470.36,2225.85 v1(2470.36,2244.37)
  Signal Layer 1 w10: J10.1@2334.52,2368.9 2353.15,2350.27 2353.15,2320.85 2364,2310 2404.73,2310 v1(2470.36,2244.37)
NetJP1_2: JP1.2 R47.1 | length 1455.3
  Top Layer w8: R47.1@2638.15,2229.57 R47.1@2638.59,2229.13
  Top Layer w20: R47.1@2638.15,2229.57 v1@2638.15,2246.91
  Signal Layer 1 w10: v1(2638.15,2243.91) 2638.15,2435.6 3107.7,2905.15 3109.87,2905.15 3113.62,2908.89 3413.62,2908.89 3558.89,2908.89 JP1.2@3650,3000
NetJP2_2: JP2.2 R48.1 | length 2269.5
  Top Layer w8: R48.1@2757.74,2131.27 R48.1@2758.18,2131.72
  Top Layer w20: R48.1@2758.18,2131.72 v1(2758.18,2151.71)
  Signal Layer 1 w10: v1(2758.18,2151.71) 2758.18,2502.91 3128.42,2873.15 4323.15,2873.15 JP2.2@4450,3000
NetJP3_2: JP3.2 R50.1 | length 1977.3
  Top Layer w10: v1(2646.23,2102.84) 2647.23,2103.84 R50.1@2647.23,2120.8
  Signal Layer 1 w10: v1(2646.23,2102.84) 2665.37,2121.99 2665.37,2435.37 3121.02,2891.02 3941.02,2891.02 JP3.2@4050,3000
NetJP4_2: JP4.2 JP4.4 JP4.6 R57.2 | length 3207.8
  Top Layer w10: R57.2@2952.3,1868.06 2952.84,1868.61 v4(2952.84,1893.18)
  Signal Layer 2 w10: JP4.6@150,2500 JP4.2@150,2300 219.38,2230.62 1637.84,2230.62 1716.75,2151.71 2007.57,2151.71 2202.18,1957.1 2581.35,1957.1 2623.65,1914.8 2688.16,1914.8 2701.27,1927.91 2885.58,1927.75 2918.82,1927.75 2952.84,1893.73 v4(2952.84,1893.18)
NetJP10_2: JP10.2 R60.2 | length 126.8
  Top Layer w8: JP10.2@1979.27,2454.69 2046.66,2387.3 R60.2@2046.66,2355.82
NetJP11_1: JP11.1 R52.1 | length 147.3
  Top Layer w10: JP11.1@1910.65,2702 1971.91,2640.73 R52.1@2032.57,2640.73
NetJP12_1: JP12.1 R51.1 | length 156.9
  Top Layer w8: R51.1@2269.93,2640.85 2277.43,2640.85 2336.52,2699.94 JP12.1@2401.09,2699.94 JP12.1@2400.18,2700.85
NetL1_1: L1.1 R3.1 R4.1 R12.2 TP6.1 TP9.1 | length 486
  Top Layer w20: v1(2320,1488.06) R12.2@2320,1552
  Signal Layer 2 w10: v1(2320,1488.06) 2342.21,1465.85 2342.21,1233.4 2333.87,1225.07 2301.01,1192.21 2301.01,1159.22 2320.51,1139.72 2333.87,1139.72 v1(2352.3,1121.29)
  other v1: 2375.42,305.15 2187.03,319.06 2356.34,388.47 2293.66,442.55 2203.57,458.86 2358.98,484.69 2210.08,534.89 2270.08,534.89 2330.08,534.89 2389.08,534.89 2180.08,564.89 2240.08,564.89 2300.08,564.89 2359.08,564.89 2210.08,594.89 2270.08,594.89 2328.08,594.89 2389.08,594.89 2180.08,624.89 2241.08,624.89 2301.08,624.89 2359.08,624.89 2210.08,654.89 2271.08,654.89 2329.08,654.89 2389.08,654.89 2180.08,684.89 2241.08,684.89 2301.08,684.89 2359.08,684.89 2210.08,714.89 2271.08,714.89 2329.08,714.89 2389.08,714.89 2180.08,744.89 2241.08,744.89 2301.08,744.89 2359.08,744.89 2210.08,774.89 2271.08,774.89 2329.08,774.89 2389.08,774.89 2180.08,804.89 2241.08,804.89 2301.08,804.89 2359.08,804.89 2210.08,834.89 2270.08,834.89 2329.08,834.89 2389.08,834.89 2180.08,864.89 2240.08,864.89 2300.08,864.89 2359.08,864.89 2210.08,894.89 2270.08,894.89 2330.08,894.89 2391.08,894.89 2240.08,924.89 2300.08,924.89 2200.51,1007.47 2330.08,1014.89 2180.08,1034.89 2300.08,1034.89 2360.08,1034.89 2420.08,1034.89 2480.08,1034.89 2540.08,1034.89 2330.08,1064.89 2390.08,1064.89 2450.08,1064.89 2510.08,1064.89 2556.73,1080.58 2299.56,1083.12 2357,1085.78 2180.08,1094.89
NetQ1A_4: Q1A.4 R58.2 | length 42.6
  Top Layer w10: R58.2@2223.3,1698.92 R58.2@2228.08,1694.14
  Top Layer w16: Q1A.4@2187.49,1698.92 R58.2@2223.3,1698.92
NetQ3A_4: Q3A.4 Q3C.9 R59.1 | length 132.2
  Top Layer w16: Q3A.4@2887.69,1025.18 R59.1@2940.08,1025.18 ; v1(2929.08,1038.3) 2930.61,1036.77 2945.58,1036.77 2947.58,1034.77 R59.1@2947.58,1033.22
  Bottom Layer w8: Q3C.9@2876.03,1031.93 Q3C.9@2880.89,1036.79 ; v1@2923.16,1038.84 2923.7,1038.3 v1(2929.08,1038.3)
  Bottom Layer w16: Q3C.9@2876.03,1019.13 Q3C.9@2876.89,1019.99 ; Q3C.9@2880.89,1036.79 2880.41,1037.15 2882.1,1038.84 v1@2923.16,1038.84
NetR18_2: R18.2 R44.1 U1.15 | length 529.1
  Top Layer w10: v1(2395.38,1842.19) 2396.03,1842.84 U1.15@2438.83,1842.84
  Top Layer w20: R18.2@2017.44,1811.01 R18.2@2024.94,1811.01 ; v1(2031.26,1788.24) 2030.49,1789 2030.49,1797.96 2024.94,1803.51 R18.2@2024.94,1811.01 ; R44.1@2071.17,1811.13 2025.06,1811.13 R18.2@2024.94,1811.01
  Signal Layer 2 w10: v1(2031.26,1788.24) 2031.26,1784.6 2048.89,1766.96 2207.06,1766.96 2217.47,1777.37 2330.56,1777.37 v1(2395.38,1842.19)
NetR24_2: R24.2 S1.2 | length 97.5
  Top Layer w10: S1.2@3615,2575 3615,2664 R24.2@3621,2670
NetR25_2: R25.2 S1.3 | length 96.2
  Top Layer w10: S1.3@3565,2575 3565,2667 R25.2@3568,2670
NetR26_2: R26.2 S1.4 | length 95
  Top Layer w10: S1.4@3515,2575 R26.2@3515,2670
NetR27_2: R27.2 S1.5 | length 96.2
  Top Layer w10: R27.2@3462,2670 3465,2667 S1.5@3465,2575
NetR28_2: R28.2 S1.6 | length 97.5
  Top Layer w10: R28.2@3409,2670 3415,2664 S1.6@3415,2575
NetR29_2: R29.2 S1.7 | length 98.7
  Top Layer w10: R29.2@3356,2670 3365,2661 S1.7@3365,2575
NetR30_2: R30.2 S1.8 | length 100.2
  Top Layer w10: R30.2@3303.61,2670.47 3315,2659.08 S1.8@3315,2575
NetR31_2: R31.2 S2.1 | length 98.7
  Top Layer w10: S2.1@4165,2575 4165,2661 R31.2@4174,2670
NetR32_2: R32.2 S2.2 | length 97.5
  Top Layer w10: S2.2@4115,2575 4115,2664 R32.2@4121,2670
NetR33_2: R33.2 S2.3 | length 96.2
  Top Layer w10: S2.3@4065,2575 4065,2667 R33.2@4068,2670
NetR34_2: R34.2 S2.4 | length 95
  Top Layer w10: S2.4@4015,2575 R34.2@4015,2670
NetR35_2: R35.2 S2.5 | length 96.2
  Top Layer w10: R35.2@3962,2670 3965,2667 S2.5@3965,2575
NetR36_2: R36.2 S2.6 | length 97.5
  Top Layer w10: R36.2@3909,2670 3915,2664 S2.6@3915,2575
NetR37_2: R37.2 S2.7 | length 98.7
  Top Layer w10: R37.2@3856,2670 3865,2661 S2.7@3865,2575
NetR38_2: R38.2 S2.8 | length 100
  Top Layer w10: R38.2@3803,2670 3815,2658 S2.8@3815,2575
nRST: JP7.2 U1.38 | length 2215.9
  Top Layer w10: U1.38@2667.17,1882.21 2687.71,1882.21 2704.03,1898.53 v1(2750.08,1898.53)
  Signal Layer 1 w8: JP7.2@1400,3000 1400,2893.26 2296.73,1996.53 2296.73,1804.08 2345.67,1755.14 2640.53,1755.14 2657.48,1772.09 2657.48,1805.93 2657.48,1816.27 2721.2,1879.99 2731.55,1879.99 v1(2750.08,1898.53)
R_FB: JP6.4 R46.2 | length 363.2
  Top Layer w10: JP6.4@1754.31,2101.32 2059.1,2101.32 R46.2@2100.43,2059.98
RT: R21.2 R49.1 U1.12 | length 365.9
  Top Layer w10: U1.12@2438.83,1901.9 2421.54,1901.9 2413.87,1909.56 2413.87,2004.64 2387.43,2031.08 2387.43,2144.99 2403.19,2160.75 2412.36,2160.75 R21.2@2417.36,2165.75 R49.1@2470.26,2165.75
SCL: J12.9 R22.1 R52.2 U1.6 | length 1493
  Top Layer w10: R52.2@2032.57,2700.73 2032.63,2700.79 2065.11,2700.79 ; v1(2065.04,2670.6) 2065.04,2700.73 2065.11,2700.79 ; J12.9@2200.67,3001.23 2097.33,2897.9 2097.33,2701.04 R22.1@2097.58,2700.79 2065.11,2700.79 ; U1.6@2543.16,1947.17 2543.16,1999.36 v1(2552.04,2008.24)
  Signal Layer 2 w10: v1(2065.04,2670.6) 2069.31,2666.33 2070.8,2666.33 2112.31,2624.82 2303.38,2624.82 2444.73,2483.47 2444.73,2093.71 2459.62,2078.82 2530.2,2008.24 v1(2552.04,2008.24)
SDA: J12.10 R23.1 R51.2 U1.5 | length 1440.2
  Top Layer w8: R23.1@2200.67,2701.1 J12.10@2200.67,2901.23
  Top Layer w10: v1(2154.38,2699.94) 2154.83,2700.4 2199.96,2700.4 R23.1@2200.42,2700.85 ; R23.1@2200.67,2701.1 R23.1@2200.42,2700.85 ; R51.2@2269.93,2700.85 R23.1@2200.42,2700.85 ; U1.5@2562.84,1947.17 2562.84,1983.86 2592.37,2013.39 v1@2592.37,2023.59
  Signal Layer 2 w10: v1(2154.38,2699.94) 2204.59,2649.73 2516.89,2649.73 2557.24,2609.37 2557.24,2146.6 2557.35,2146.5 2557.35,2125.89 2557.24,2125.79 2557.24,2065.74 v1(2593.31,2029.67)
SLOPE: JP8.1 R20.2 U1.9 | length 468
  Top Layer w10: U1.9@2484.1,1947.17 2484.1,2028.85 2500.64,2045.39 2500.64,2166.52 ; JP8.1@2500.64,2377.56 2500.64,2166.52 ; R20.2@2531.4,2166.52 2500.64,2166.52
SS/ATRK: C20.1 TP12.1 U1.2 | length 533.4
  Top Layer w10: U1.2@2621.9,1947.17 2621.9,1964.49 2684.02,2026.62 v1(2720.52,2026.62)
  Signal Layer 2 w10: v1(2720.52,2026.62) 2799.36,2105.46 2941.66,2105.46 3035.67,2199.46 TP12.1@3040.7,2199.46
SW1: C24.1 NT2.1 U1.23 | length 257.8
  Top Layer w10: 2478.66,1671.27 2503.79,1696.4 U1.23@2503.79,1718.83
  Top Layer w20: NT2.1@2329.97,1582.63 2352.85,1582.63 2353.1,1582.87 2414.23,1582.87 2425.94,1594.59 2425.94,1620 ; C24.1@2426.67,1619.27 2478.66,1671.27
SW2: C23.2 C25.1 D1.2 L1.2 Q3.5-6-7-8 Q3A.5-6-7-8 Q3B.5-6-7-8 Q3C.5-6-7-8 Q4.1-2-3 TP7.1 U1.33 | length 465.8
  Top Layer w10: U1.33@2667.17,1783.79 2692.93,1783.79 2714.67,1762.05 2714.67,1701.5
  Top Layer w20: C25.1@2712.04,1608 2722.44,1608 2827.13,1503.32 2827.13,1406.33 Q4.1-2-3@2828.83,1404.63 ; C25.1@2714.67,1610.62 2714.67,1631.96 2714.67,1701.5
  other v1: 2823.15,318.88 2658.72,328.14 2664.89,431.35 2824.6,449.08 2747,476 2630.08,534.89 2690.08,534.89 2750.08,534.89 2810.08,534.89 2662.08,564.89 2720.08,564.89 2780.08,564.89 2838.08,564.89 2632.08,594.89 2692.08,594.89 2750.08,594.89 2810.08,594.89 2662.08,624.89 2720.08,624.89 2780.08,624.89 2838.08,624.89 2632.08,654.89 2692.08,654.89 2750.08,654.89 2810.08,654.89 2662.08,684.89 2720.08,684.89 2780.08,684.89 2632.08,714.89 2692.08,714.89 2750.08,714.89 2810.08,714.89 2662.08,744.89 2720.08,744.89 2780.08,744.89 2838.08,744.89 2632.08,774.89 2692.08,774.89 2750.08,774.89 2810.08,774.89 2662.08,804.89 2720.08,804.89 2780.08,804.89 2838.08,804.89 2632.08,834.89 2692.08,834.89 2750.08,834.89 2810.08,834.89 2662.08,864.89 2720.08,864.89 2780.08,864.89 2840.08,864.89 2632.08,894.89 2690.08,894.89 2750.08,894.89 2810.08,894.89 2660.08,924.89 2720.08,924.89 2780.08,924.89 2840.08,924.89 2690.08,954.89 2750.08,954.89 2810.08,954.89 2782.25,1025.27 2727.77,1028.84 2660.08,1044.89 2690.08,1074.89 2750.08,1074.89 2810.08,1074.89 2782.25,1085.78 2811.95,1105.41 2714.76,1108.99 2840.08,1117.09 2780.95,1119.93 2690.08,1134.89 2750.08,1134.89 2810.08,1134.89 2840.75,1147.38 2780.61,1150.21 2720.08,1164.89 2810.08,1165.86 2840.08,1177.09 2780.95,1179.93 2690.08,1194.89 2750.08,1194.89 2810.08,1194.89 2770.46,1223.99 2660.08,1224.89 2720.08,1224.89 2690.08,1254.89 2750.08,1254.89 2660.08,1284.89 2720.08,1284.89 2687.27,1312.99 2756.28,1327.82 2707.98,1340.97 2660.08,1344.89 2758.18,1363.54 2690.08,1374.89 2722.04,1393.03 2660.08,1404.89 2758.18,1413.37 2723.31,1434.26 2690.08,1434.89
  other v3: 2781.39,980.69 2815.07,997.48
SYNC: C35.1 R48.2 TP11.1 U1.3 | length 466.1
  Top Layer w10: U1.3@2602.21,1947.17 2602.21,1972.68 2638.61,2009.08 2641.21,2009.08 2677.6,2045.47 2677.6,2053.71 2687.61,2063.72 2698.56,2063.72 C35.1@2703.56,2068.72 R48.2@2756.28,2068.72 2831.31,2068.72 2870.29,2107.69 TP11.1@2870.29,2219.44
VBUS: J12.5 R22.2 R23.2 | length 746.7
  Top Layer w8: R22.2@2097.64,2640.85 R23.2@2200.92,2640.85 2208.42,2640.85 2239.9,2609.37 2309.57,2609.37
  Top Layer w10: 2309.57,2609.37 2345.22,2645.02 2382.03,2645.02 2382.3,2645.3 2431.68,2645.3 2451,2664.62 2451,2950.9 J12.5@2400.67,3001.23
VCC1: C17.2 J13.1 U1.1 | length 2881.6
  Top Layer w10: U1.1@2641.58,1947.17 v1(2661.1,1947.17) 2670.93,1947.17 C17.2@2693.76,1970.01
  Signal Layer 2 w10: v1(2661.1,1947.17) 2661.1,2031.74 2710.87,2081.51 2710.87,2494.14 3089.88,2873.15 4631.15,2873.15 J13.1@4755,2997
VCC2: C39.2 D3.2 D4.2 JP1.3 JP2.3 JP3.3 JP6.5 JP9.3 R16.2 TP10.1 U1.29 | length 7259.3
  Top Layer w10: v1(2560,1536.5) 2560,1554.12 2573,1567.12 C39.2@2573,1587.49 2621.9,1636.39 U1.29@2621.9,1718.83
  Top Layer w15: R16.2@2888.51,2793.22 2886.01,2795.72 2886.01,2805.92 2868.51,2823.42 2868.51,3026.04 2933.76,3091.29 3458.71,3091.29 JP1.3@3550,3000
  Top Layer w20: D3.2@2538.31,1536.5 v1(2560,1536.5) D4.2@2585.69,1536.5
  Signal Layer 1 w20: TP10.1@1700,2450.86 1754.31,2396.54 JP6.5@1754.31,2201.32 ; v1(2418.56,2035.87) 2418.56,2034.79 2408.95,2025.18 2408.95,1995.59 2433.73,1970.81 2605.66,1970.81 2703.56,2068.72 2801.91,2068.72 2914.72,1955.91 2914.72,1868.66 v1(2899.86,1853.8)
  Signal Layer 2 w20: v1(2418.56,2035.87) 2282.67,2035.87 2117.23,2201.32 JP6.5@1754.31,2201.32 1754.31,2396.54 TP10.1@1700,2450.86 JP9.3@1700,3000 1791.29,3091.29 3550,3091.29 ; v1(2560,1536.5) 2676.77,1536.5 2703.55,1563.28 2703.55,1594.89 2899.86,1791.2 v1(2899.86,1853.8) ; JP1.3@3550,3000 3550,3091.29 ; JP3.3@3950,3000 3950,3091.29 ; JP2.3@4350,3000 4258.71,3091.29 3950,3091.29 ; 3550,3091.29 3950,3091.29
VEXT: J7.1 JP4.1 | length 881.6
  Signal Layer 1 w10: JP4.1@250,2300 314.17,2364.17 314.17,2776.62 537.56,3000 J7.1@600,3000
